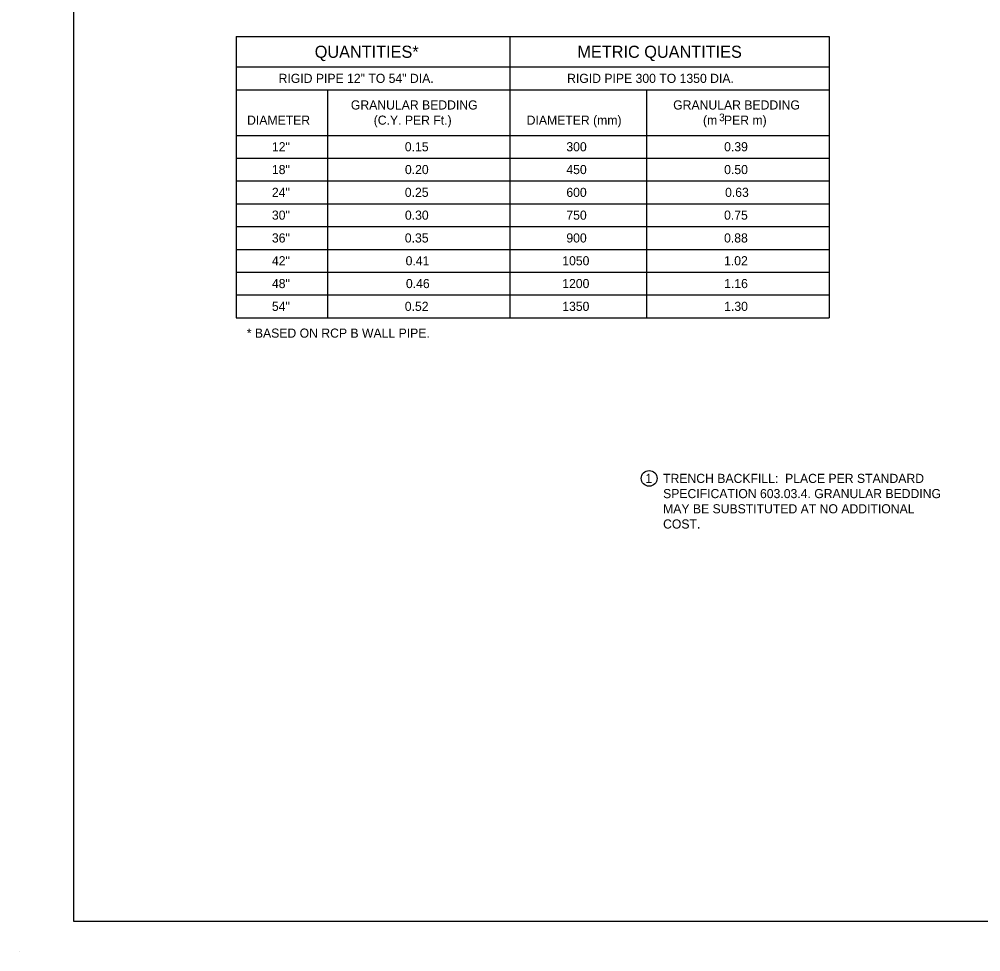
# Model space of a CAD drawing. Extents: x 49991.4 to 50061.4, y 49960.6 to 50011.4.
# Drawn here: x 49999.02 to 50005.35, y 49987.6 to 49993.73 of the extents above; entities that cross this region are included whole.
import ezdxf

# ---------------------------------------------------------------- set-up
doc = ezdxf.new("R2010")
doc.units = 0
doc.layers.add('Level 1', color=7, linetype='Continuous')
doc.layers.add('Level 2', color=7, linetype='Continuous')

msp = doc.modelspace()

# ---------------------------------------------------------------- linework, layer by layer
at = {"layer": 'Level 1'}
msp.add_line((49999.0245, 49987.5988), (49999.0245, 49987.5988), dxfattribs=at)
msp.add_lwpolyline([(49999.3835, 49998.9992), (50016.7501, 49998.9992), (50016.7501, 49987.7988), (49999.3835, 49987.7988)], close=True, dxfattribs=at)
at = {"layer": 'Level 2'}
for p, q in [((50000.4517, 49993.6201), (50000.4517, 49991.7701)), ((50000.4518, 49993.6201), (50004.3517, 49993.6201)), ((50002.2517, 49993.6201), (50002.2517, 49991.7701)), ((50004.3517, 49993.6201), (50004.3517, 49991.7701)), ((50000.4517, 49993.4201), (50004.3517, 49993.4201)), ((50000.4517, 49993.2701), (50004.3517, 49993.2701)), ((50001.0517, 49993.2701), (50001.0517, 49991.7701)), ((50003.1517, 49993.2701), (50003.1517, 49991.7701)), ((50000.4517, 49992.9701), (50004.3517, 49992.9701)), ((50000.4517, 49992.8201), (50004.3517, 49992.8201)), ((50000.4517, 49992.6701), (50004.3517, 49992.6701)), ((50000.4517, 49992.5201), (50004.3517, 49992.5201)), ((50000.4517, 49992.3701), (50004.3517, 49992.3701)), ((50000.4517, 49992.2201), (50004.3517, 49992.2201)), ((50000.4517, 49992.0701), (50004.3517, 49992.0701)), ((50000.4517, 49991.9201), (50004.3517, 49991.9201)), ((50000.4517, 49991.7701), (50004.3517, 49991.7701))]:
    msp.add_line(p, q, dxfattribs=at)
msp.add_circle((50003.1681, 49990.7132), 0.0517, dxfattribs=at)

# ---------------------------------------------------------------- texts
for s, height, p in [('QUANTITIES*', 0.08, (50000.9682, 49993.4801)), ('METRIC QUANTITIES', 0.08, (50002.6962, 49993.4801)), ('RIGID PIPE 12" TO 54" DIA.', 0.06, (50000.7307, 49993.3151)), ('RIGID PIPE 300 TO 1350 DIA.', 0.06, (50002.6284, 49993.3151)), ('GRANULAR BEDDING', 0.06, (50001.2061, 49993.1401)), ('GRANULAR BEDDING', 0.06, (50003.3262, 49993.1401)), ('DIAMETER', 0.06, (50000.5233, 49993.0401)), ('(C.Y. PER Ft.)', 0.06, (50001.3563, 49993.0401)), ('DIAMETER (mm)', 0.06, (50002.3625, 49993.0401)), ('(m  PER m)', 0.06, (50003.5222, 49993.0401)), ('3', 0.05, (50003.6283, 49993.0633)), ('12"', 0.06, (50000.6867, 49992.8651)), ('0.15', 0.06, (50001.561, 49992.8651)), ('300', 0.06, (50002.6235, 49992.8651)), ('0.39', 0.06, (50003.6614, 49992.8651)), ('18"', 0.06, (50000.6867, 49992.7151)), ('0.20', 0.06, (50001.5616, 49992.7151)), ('450', 0.06, (50002.6235, 49992.7151)), ('0.50', 0.06, (50003.6616, 49992.7151)), ('24"', 0.06, (50000.6867, 49992.5651)), ('0.25', 0.06, (50001.561, 49992.5651)), ('600', 0.06, (50002.6235, 49992.5651)), ('0.63', 0.06, (50003.6675, 49992.5651)), ('30"', 0.06, (50000.6867, 49992.4151)), ('0.30', 0.06, (50001.5616, 49992.4151)), ('750', 0.06, (50002.6235, 49992.4151)), ('0.75', 0.06, (50003.661, 49992.4151)), ('36"', 0.06, (50000.6867, 49992.2651)), ('0.35', 0.06, (50001.561, 49992.2651)), ('900', 0.06, (50002.6235, 49992.2651)), ('0.88', 0.06, (50003.661, 49992.2651)), ('42"', 0.06, (50000.6867, 49992.1151)), ('0.41', 0.06, (50001.5662, 49992.1151)), ('1050', 0.06, (50002.5965, 49992.1151)), ('1.02', 0.06, (50003.6608, 49992.1151)), ('48"', 0.06, (50000.6867, 49991.9651)), ('0.46', 0.06, (50001.5682, 49991.9651)), ('1200', 0.06, (50002.5965, 49991.9651)), ('1.16', 0.06, (50003.6614, 49991.9651)), ('54"', 0.06, (50000.6867, 49991.8151)), ('0.52', 0.06, (50001.5608, 49991.8151)), ('1350', 0.06, (50002.5965, 49991.8151)), ('1.30', 0.06, (50003.6616, 49991.8151)), ('* BASED ON RCP B WALL PIPE.', 0.06, (50000.5212, 49991.639)), ('1', 0.06, (50003.143, 49990.6832)), ('TRENCH BACKFILL:  PLACE PER STANDARD ', 0.06, (50003.2598, 49990.6832)), ('SPECIFICATION 603.03.4. GRANULAR BEDDING', 0.06, (50003.2598, 49990.5832)), ('MAY BE SUBSTITUTED AT NO ADDITIONAL', 0.06, (50003.2598, 49990.4832)), ('COST.', 0.06, (50003.2598, 49990.3832))]:
    msp.add_text(s, height=height, dxfattribs=at).set_placement(p)

doc.saveas('drawing.dxf')
